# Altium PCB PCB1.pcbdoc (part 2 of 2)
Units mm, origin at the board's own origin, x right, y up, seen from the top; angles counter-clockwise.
Board outline 53.72 x 80.14 mm, 2 copper layers (Top Layer, Bottom Layer); 37 components, 55 nets, 218 pads, 259 vias.
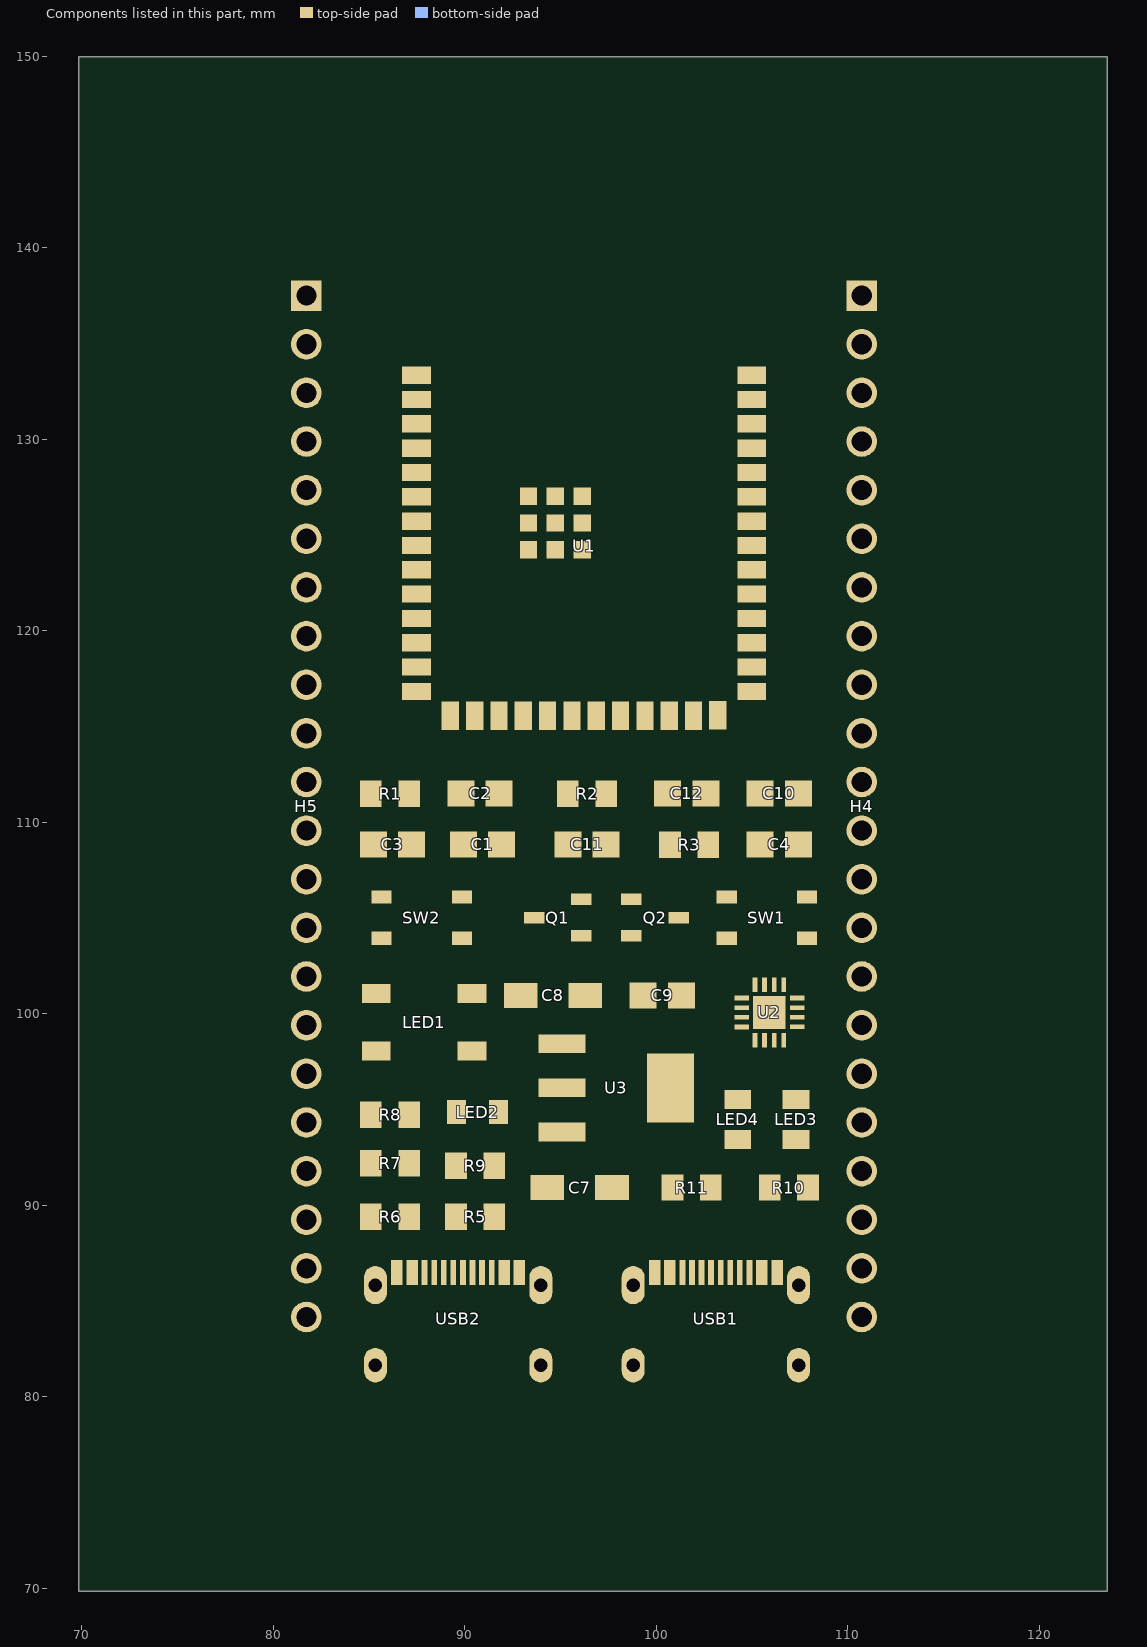
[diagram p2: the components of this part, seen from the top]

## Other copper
Top Layer:
  region net 5V_IN: 100.763,85.614 100.913,85.614 101.024,85.839 100.724,85.839
  region net $1N2384: 101.949,87.364 101.799,87.364 101.724,87.139 102.024,87.139
  region net CH_USB-: 102.449,87.364 102.299,87.364 102.224,87.139 102.524,87.139
  region net CH_USB-: 102.449,85.614 102.524,85.839 102.224,85.839 102.299,85.614
  region net CH_USB+: 102.949,87.364 102.799,87.364 102.724,87.139 103.024,87.139
  region net CH_USB-: 103.299,85.614 103.449,85.614 103.524,85.839 103.224,85.839
  region net CH_USB+: 103.961,87.364 103.811,87.364 103.724,87.139 104.024,87.139
  region net $1N2366: 104.977,87.364 104.827,87.364 104.724,87.139 105.024,87.139
  region net 5V_IN: 105.512,85.614 105.524,85.839 105.224,85.839 105.362,85.614
  region net 5V_IN: 105.589,87.364 105.524,87.139 105.824,87.139 105.739,87.364
  region net 3V3: 92.055,110.277 91.555,110.277 91.227,109.527 92.637,109.527
  region net 3V3: 92.025,112.73 91.525,112.73 91.1,112.194 92.51,112.194
  region net 3V3: 92.055,110.094 92.51,110.844 91.1,110.844 91.555,110.094
  region net CHIP_UP: 85.108,110.592 85.296,110.817 84.771,110.817 84.958,110.592
  region net CHIP_UP: 84.963,112.405 84.788,112.195 85.278,112.195 85.103,112.405
  region net CHIP_UP: 85.108,109.752 84.958,109.752 84.771,109.527 85.296,109.527
  region net CHIP_UP: 85.054,107.952 85.242,108.177 84.717,108.177 84.904,107.952
  region net CH_TX: 103.897,99.4 103.897,99.25 104.093,99.2 104.093,99.45
  region net CH_RX: 104.818,98.701 104.818,98.551 105.043,98.364 105.043,98.889
  region net $1N3062: 105.593,98.048 105.743,98.048 105.793,98.251 105.543,98.251
  region net CH_USB-: 106.952,98.109 106.952,98.321 106.793,99.001 106.545,98.251
  region net 5V_IN: 107.968,99.251 107.968,99.401 107.743,99.451 107.743,99.201
  region net DTR: 107.968,100.9 107.743,100.95 107.743,100.7 107.968,100.75
  region net RTS: 107.018,101.675 106.793,101.862 106.793,101.338 107.018,101.525
  region net RTS: 102.002,108.008 102.198,107.991 102.622,108.15 102.161,108.432
  region net $1N2059: 100.652,107.992 100.802,107.992 100.99,108.15 100.465,108.15
  region net CHIP_UP: 92.874,105.036 92.874,104.886 93.099,104.729 93.099,105.223
  region net CHIP_UP: 94.269,105.104 94.169,105.291 94.169,104.767 94.269,104.954
  region net $1N2059: 99.067,106.438 98.643,106.279 99.249,106.143 99.279,106.438
  region net DTR: 98.789,103.554 98.976,103.779 98.451,103.779 98.639,103.554
  region net DTR: 97.954,104.215 97.954,104.065 98.179,103.878 98.179,104.379
  region net GPIO0: 101.944,104.977 101.719,105.164 101.719,104.729 101.944,104.827
  region net 3V3: 107.576,107.727 107.951,108.177 106.901,108.177 107.276,107.727
  region net 5V_IN: 93.529,94.092 93.847,93.349 94.246,94.329 93.529,94.516
  region net 5V_IN: 94.476,92.899 94.776,92.899 95.151,93.349 94.101,93.349
  region net 5V_IN: 96.767,93.689 96.767,93.989 96.317,94.329 96.317,93.349
  region net 5V_IN: 94.367,89.862 94.742,90.284 93.692,90.284 94.067,89.862
  region net 5V_IN: 94.176,89.834 94.476,89.834 94.851,90.284 93.801,90.284
  region net 5V_IN: 94.476,92.03 94.101,91.58 95.151,91.58 94.776,92.03
  region net 3V3: 94.107,99.999 93.807,100.829 92.834,100.317 93.683,99.999
  region net GPIO48: 91.149,101.727 90.937,101.727 90.513,101.568 91.134,101.447
  region net 5V_IN: 87.301,85.614 87.451,85.614 87.562,85.839 87.262,85.839
  region net $1N3528: 88.487,87.229 88.337,87.229 88.262,87.139 88.562,87.139
  region net GPIO19: 88.987,87.364 88.837,87.364 88.762,87.139 89.062,87.139
  region net GPIO19: 88.987,85.614 89.062,85.839 88.762,85.839 88.837,85.614
  region net GPIO20: 89.337,87.364 89.262,87.139 89.562,87.139 89.487,87.364
  region net GPIO19: 89.987,85.614 90.062,85.839 89.762,85.839 89.837,85.614
  region net GPIO20: 90.337,87.364 90.262,87.139 90.562,87.139 90.487,87.364
  region net GPIO20: 90.487,85.614 90.562,85.839 90.262,85.839 90.337,85.614
  region net $1N3525: 91.487,87.364 91.337,87.364 91.262,87.139 91.562,87.139
  region net 5V_IN: 92.01,85.614 92.062,85.839 91.762,85.839 91.86,85.614
  region net $1N3528: 86.439,93.894 86.864,94.053 86.54,94.472 86.381,94.048
  region net GPIO0: 107.367,112.419 107.18,112.194 107.704,112.194 107.517,112.419
  region net GPIO0: 108.343,110.746 108.131,111.312 107.609,110.844 108.174,110.632
  region net GPIO0: 108.716,106.204 108.416,106.454 108.416,105.754 108.716,106.004
  region net GPIO0: 108.595,106.666 108.312,106.666 107.746,106.454 108.416,106.134
  region net CHIP_UP: 85.254,106.613 85.042,106.613 85.132,106.258 85.678,106.454
  region net CHIP_UP: 86.407,106.179 86.182,106.366 86.182,105.841 86.407,106.029
  region net CHIP_UP: 89.107,106.179 89.107,106.029 89.332,105.841 89.332,106.366
  region net CHIP_UP: 90.541,105.907 90.382,106.454 90.217,105.754 90.541,105.695
  region net CHIP_UP: 94.832,108.019 95.043,108.018 95.468,108.177 94.725,108.177
  region net 5V_IN: 103.53,111.708 103.305,111.895 103.305,111.371 103.53,111.558
  region net GPIO1: 109.942,135.023 109.725,134.064 109.831,133.958 110.79,134.175
  region net GPIO2: 109.942,132.483 109.725,131.524 109.831,131.418 110.79,131.635
  region net CH_TX: 110.79,128.151 109.871,128.328 109.765,128.222 109.942,127.303
  region net GPIO42: 111.056,125.548 110.049,125.991 109.905,125.923 109.971,125.035
  region net GPIO41: 111.252,122.888 110.692,123.317 110.542,123.317 110.066,122.704
  region net GPIO40: 110.79,120.531 109.831,120.748 109.725,120.642 109.942,119.683
  region net GPIO39: 110.79,117.991 109.831,118.208 109.725,118.102 109.942,117.143
  region net GPIO38: 110.239,115.277 109.41,115.327 109.4,115.124 110.184,114.078
  region net GPIO37: 111.34,112.642 110.815,113.034 110.665,113.034 110.14,112.642
  region net GPIO36: 110.79,110.371 109.831,110.588 109.725,110.482 109.942,109.523
  region net GPIO35: 110.79,107.831 109.831,108.048 109.725,107.942 109.942,106.983
  region net GPIO0: 111.251,105.108 110.249,105.793 110.004,105.755 110.066,104.923
  region net GPIO45: 110.79,102.751 109.831,102.968 109.725,102.862 109.942,101.903
  region net GPIO47: 111.538,96.823 111.755,97.782 111.649,97.888 110.69,97.671
  region net GPIO20: 110.102,91.31 110.059,90.48 110.256,90.465 111.299,91.221
  region net GPIO19: 110.211,89.853 109.7,89.328 109.7,89.178 110.211,88.653
  region net 3V3: 83.29,137.763 82.54,138.313 82.54,136.713 83.29,137.263
  region net 3V3: 82.29,134.392 83.109,134.751 83.091,135.251 82.248,135.591
  region net CHIP_UP: 82.269,131.833 83.1,132.358 83.1,132.508 82.269,133.033
  region net GPIO4: 82.269,129.293 83.1,129.818 83.1,129.968 82.269,130.493
  region net GPIO5: 82.269,126.753 82.854,127.278 82.854,127.428 82.269,127.953
  region net GPIO6: 82.539,124.853 82.696,125.79 82.578,125.884 81.601,125.601
  region net GPIO7: 82.429,122.68 82.458,123.52 82.28,123.554 81.25,122.906
  region net GPIO15: 82.517,119.925 82.595,120.821 82.455,120.894 81.453,120.48
  region net GPIO16: 82.538,117.143 82.755,118.102 82.649,118.208 81.69,117.991
  region net GPIO17: 82.538,114.603 82.755,115.562 82.649,115.668 81.69,115.451
  region net GPIO18: 82.538,112.063 82.755,113.022 82.649,113.128 81.69,112.911
  region net GPIO8: 82.538,109.523 82.755,110.482 82.649,110.588 81.69,110.371
  region net GPIO3: 82.538,106.983 82.755,107.942 82.649,108.048 81.69,107.831
  region net GPIO46: 82.538,104.443 82.755,105.402 82.649,105.508 81.69,105.291
  region net GPIO9: 82.538,101.903 82.755,102.862 82.649,102.968 81.69,102.751
  region net GPIO10: 82.538,99.363 82.755,100.322 82.649,100.428 81.69,100.211
  region net GPIO11: 82.538,96.823 82.755,97.782 82.649,97.888 81.69,97.671
  region net GPIO12: 82.538,94.283 82.772,95.224 82.631,95.365 81.69,95.131
  region net GPIO13: 82.538,91.743 82.755,92.702 82.649,92.808 81.69,92.591
  region net 5V_IN: 82.538,86.663 82.808,87.569 82.596,87.781 81.69,87.511
  region net $1N5776: 90.96,94.12 91.19,93.926 92.038,94.244 91.278,94.969
  region net $1N5776: 89.921,93.082 88.985,92.764 90.117,92.323 90.346,93.082
  region net CH_RX: 106.39,95.683 106.615,95.496 106.615,96.02 106.39,95.833
  region net $1N6033: 107.113,92.713 107.263,92.713 107.45,92.938 106.926,92.938
  region net CH_TX: 104.192,96.263 104.005,96.038 104.529,96.038 104.342,96.263
  region net 3V3: 106.084,89.932 106.459,90.243 105.409,90.243 105.784,89.932
  region net $1N6033: 107.361,91.78 107.368,91.508 107.998,91.621 107.573,91.78
  region net CHIP_UP: 86.515,130.89 86.515,130.74 86.74,130.552 86.74,131.077
  region net GPIO4: 86.515,129.968 86.515,129.818 86.74,129.631 86.74,129.995
  region net GPIO5: 86.515,128.35 86.515,128.2 86.74,128.012 86.74,128.537
  region net GPIO6: 86.515,127.075 86.515,126.925 86.74,126.738 86.74,127.262
  region net GPIO7: 86.515,125.406 86.74,125.285 86.74,125.743 86.515,125.556
  region net GPIO15: 86.515,124.54 86.515,124.39 86.74,124.202 86.74,124.727
  region net GPIO17: 86.515,122.104 86.74,121.916 86.74,122.375 86.515,122.254
  region net GPIO18: 86.515,120.73 86.515,120.58 86.74,120.392 86.74,120.917
  region net GPIO8: 86.515,119.564 86.74,119.376 86.74,119.835 86.515,119.714
  region net GPIO19: 86.515,118.19 86.515,118.04 86.74,117.852 86.74,118.377
  region net GPIO20: 86.515,116.92 86.515,116.77 86.74,116.582 86.74,117.107
  region net GPIO3: 88.769,114.656 88.981,114.656 89.405,114.815 88.805,114.957
  region net GPIO46: 90.45,114.655 90.6,114.655 90.787,114.815 90.263,114.815
  region net GPIO9: 91.72,114.59 91.87,114.59 92.057,114.815 91.533,114.815
  region net GPIO10: 93.267,114.59 93.454,114.815 92.93,114.815 93.117,114.59
  region net GPIO21: 99.614,114.656 99.826,114.656 99.865,114.882 98.965,114.815
  region net GPIO47: 100.76,114.59 100.947,114.815 100.423,114.815 100.61,114.59
  region net GPIO45: 103.834,115.092 103.675,115.516 103.604,114.845 103.834,114.88
  region net GPIO0: 105.965,116.765 105.965,116.915 105.74,117.102 105.74,116.578
  region net GPIO35: 105.965,118.04 105.965,118.19 105.74,118.377 105.74,117.852
  region net GPIO36: 105.965,119.31 105.965,119.46 105.74,119.647 105.74,119.122
  region net GPIO37: 105.965,120.58 105.965,120.73 105.74,120.917 105.74,120.392
  region net GPIO38: 105.965,121.85 105.965,122 105.74,122.187 105.74,121.662
  region net GPIO39: 105.965,123.12 105.965,123.27 105.74,123.457 105.74,122.932
  region net GPIO40: 105.965,124.39 105.965,124.54 105.74,124.727 105.74,124.202
  region net GPIO41: 105.965,125.937 105.74,126.124 105.74,125.599 105.965,125.787
  region net GPIO42: 105.965,126.93 105.965,127.08 105.74,127.267 105.74,126.742
  region net CH_TX: 105.965,128.2 105.965,128.35 105.74,128.537 105.74,128.012
  region net GPIO2: 105.965,130.74 105.965,130.89 105.74,131.077 105.74,130.552
  region net GPIO1: 105.965,132.01 105.965,132.16 105.74,132.347 105.74,131.822
  region net CH_TX: 105.192,128.046 105.509,128.2 105.509,128.35 105.192,128.504
  region net 5V_IN: 87.491,86.691 87.412,87.008 87.112,87.008 87.033,86.691
  region net 5V_IN: 87.125,86.217 87.301,85.946 87.451,86.006 87.55,86.387
  region net 5V_IN: 100.953,86.691 100.874,87.008 100.574,87.008 100.495,86.691
  region net 5V_IN: 100.587,86.217 100.763,85.946 100.913,86.006 101.012,86.387
  region net 5V_IN: 105.247,86.349 105.362,85.984 105.512,85.94 105.686,86.219
  region net 5V_IN: 105.82,86.551 105.739,86.95 105.589,87.027 105.413,86.761
  region net $1N3528: 86.877,94.761 86.761,94.428 86.867,94.322 87.2,94.438
  region net $1N3525: 90.52,90.502 90.683,90.221 90.833,90.36 90.856,90.812
  region net GPIO0: 107.587,106.123 107.523,105.842 107.629,105.736 107.91,105.8
  region net GPIO0: 108.093,105.875 108.41,106.004 108.41,106.204 108.093,106.333
  region net GPIO0: 108.195,106.085 108.328,106.4 108.187,106.541 107.872,106.408
  region net GPIO0: 103.762,105.807 104.08,105.736 104.155,105.873 103.976,106.212
  region net GPIO0: 103.387,106.123 103.271,105.79 103.377,105.684 103.71,105.8
  region net CHIP_UP: 84.805,114.352 84.963,114.035 85.103,114.035 85.262,114.352
  region net CHIP_UP: 87.288,131.044 86.971,130.89 86.971,130.74 87.288,130.586
  region net GPIO12: 86.385,99.493 86.514,99.176 86.714,99.176 86.843,99.493
  region net 3V3: 107.216,108.669 107.276,108.339 107.576,108.291 107.668,108.598
  region net 5V_IN: 102.818,111.404 103.135,111.558 103.135,111.708 102.818,111.862
  region net RTS: 99.262,104.8 99.579,104.954 99.579,105.104 99.262,105.258
  region net $1N3062: 105.46,97.517 105.576,97.85 105.47,97.956 105.137,97.84
  region net 5V_IN: 102.541,99.67 102.224,99.591 102.224,99.291 102.541,99.212
  region net 5V_IN: 102.762,99.745 102.542,99.748 102.436,99.642 102.439,99.422
  region net 5V_IN: 102.97,99.237 103.25,99.574 103.228,99.764 102.917,99.691
  region net DTR: 101.271,102.845 100.954,102.691 100.954,102.541 101.271,102.387
  region net GPIO48: 91.846,104.065 92,103.748 92.15,103.748 92.304,104.065
  region net GPIO48: 92.05,105.866 91.896,106.183 91.746,106.183 91.592,105.866
  region net GPIO19: 87.784,98.01 87.959,97.745 88.109,97.83 88.182,98.235
  region net GPIO20: 88.723,98.317 88.607,97.984 88.713,97.878 89.046,97.994
  region net GPIO19: 87.986,101.675 87.832,101.854 87.682,101.854 87.528,101.675
  region net GPIO20: 88.815,101.727 88.642,102.009 88.492,101.969 88.373,101.609
  region net GPIO20: 88.468,105.542 88.492,105.091 88.642,104.954 88.806,105.234
  region net GPIO19: 87.992,104.471 88.212,104.468 88.318,104.574 88.315,104.794
  region net GPIO19: 87.642,106.956 87.707,107.266 87.533,107.304 87.195,107.053
  region net GPIO20: 88.494,107.009 88.34,107.326 88.19,107.326 88.036,107.009
  region net $1N2384: 101.454,87.58 101.787,87.464 101.893,87.57 101.777,87.903
  region net 3V3: 106.157,90.105 106.084,90.426 105.784,90.442 105.7,90.129
  region net CH_USB-: 102.145,88.952 102.299,88.635 102.449,88.635 102.603,88.952
  region net CH_USB+: 103.657,88.952 103.811,88.635 103.961,88.635 104.115,88.952
  region net CH_USB+: 107.296,97.059 107.091,97.104 106.985,96.998 106.891,96.845
  region net CH_USB-: 107.29,97.865 107.136,98.106 106.986,98.106 106.832,97.865
  region net $1N2366: 104.673,88.063 104.827,87.746 104.977,87.746 105.131,88.063
  region net CH_TX: 103.149,98.604 103.303,98.287 103.453,98.287 103.607,98.604
  region net CH_TX: 103.682,98.787 103.798,99.12 103.692,99.226 103.359,99.11
  region net CH_RX: 104.038,98.35 104.192,98.033 104.342,98.033 104.496,98.35
  region net CH_RX: 104.518,98.379 104.802,98.551 104.764,98.701 104.407,98.823
  region net GPIO45: 106.677,107.721 106.501,107.988 106.351,107.92 106.261,107.53
  region net 3V3: 105.498,106.642 105.853,106.657 105.991,106.957 105.689,107.058
  region net 3V3: 104.927,104.954 105.006,104.637 105.306,104.637 105.385,104.954
  region net CH_RX: 106.02,103.453 105.866,103.77 105.716,103.77 105.562,103.453
  region net CH_RX: 108.916,105.302 108.913,105.082 109.019,104.976 109.239,104.979
  region net GPIO45: 106.451,104.192 106.605,103.886 106.755,103.886 106.909,104.192
  region net CH_TX: 102.845,105.866 102.691,106.183 102.541,106.183 102.387,105.866
  region net CH_TX: 103.53,114.044 103.684,113.727 103.834,113.727 103.988,114.044
  region net CH_TX: 103.988,112.851 103.834,113.168 103.684,113.168 103.53,112.851
  region net CH_TX: 103.359,109.805 103.692,109.689 103.798,109.795 103.682,110.128
  region net 5V_IN: 104.54,107.238 104.32,107.241 104.214,107.135 104.217,106.915
  region net 5V_IN: 103.756,104.992 103.706,104.701 103.871,104.654 104.208,104.921
  region net GPIO48: 99.543,108.025 99.389,108.342 99.239,108.342 99.085,108.025
  region net GPIO48: 108.223,102.285 108.003,102.288 107.897,102.182 107.9,101.962
  region net GPIO48: 99.01,114.065 99.007,113.845 99.113,113.739 99.333,113.742
  region net GPIO48: 99.112,114.275 98.795,114.121 98.795,113.971 99.112,113.817
  region net GPIO21: 101.922,110.344 101.653,110.543 101.547,110.437 101.47,110.273
  region net GPIO3: 83.591,110.288 83.745,109.971 83.895,109.971 84.049,110.288
  region net GPIO3: 88.569,114.027 88.685,114.36 88.579,114.466 88.246,114.35
  region net GPIO46: 83.591,107.748 83.745,107.431 83.895,107.431 84.049,107.748
  region net GPIO46: 89.585,113.392 89.701,113.725 89.595,113.831 89.262,113.715
  region net GPIO9: 84.099,105.97 84.253,105.653 84.403,105.653 84.557,105.97
  region net GPIO9: 89.864,110.007 90.181,110.161 90.181,110.311 89.864,110.465
  region net GPIO10: 83.897,102.762 83.894,102.542 84,102.436 84.22,102.439
  region net GPIO10: 84.505,102.724 84.508,102.944 84.402,103.05 84.182,103.047
  region net GPIO10: 85.904,103.226 85.587,103.072 85.587,102.922 85.904,102.768
  region net GPIO10: 89.737,102.768 90.054,102.922 90.054,103.072 89.737,103.226
  region net GPIO10: 90.83,104.065 90.984,103.748 91.134,103.748 91.288,104.065
  region net GPIO10: 91.288,106.7 91.134,106.934 90.984,106.934 90.83,106.7
  region net GPIO47: 109.041,117.373 109.22,117.527 109.22,117.677 109.041,117.831
  region net GPIO47: 102.033,113.767 101.727,113.613 101.727,113.463 102.033,113.309
  region net GPIO47: 100.456,115.363 100.61,115.047 100.76,115.047 100.914,115.363
  region net RTS: 107.24,101.829 106.923,101.675 106.923,101.525 107.24,101.371
  region net GPIO21: 108.604,97.84 108.271,97.956 108.165,97.85 108.281,97.517
  region net GPIO21: 107.489,98.279 107.809,98.206 107.882,98.345 107.703,98.684
  region net RTS: 108.356,95.683 108.51,95.366 108.66,95.366 108.814,95.683
  region net RTS: 98.45,98.096 98.604,97.779 98.754,97.779 98.908,98.096
  region net GPIO19: 89.244,85.347 88.965,85.385 88.906,85.232 89.173,84.895
  region net GPIO19: 89.643,84.895 89.91,85.232 89.859,85.393 89.572,85.347
  region net GPIO19: 90.988,82.814 91.317,82.959 91.329,83.109 91.024,83.27
  region net GPIO20: 90.663,85.315 90.487,85.581 90.337,85.504 90.255,85.106
  region net GPIO20: 91.896,83.464 92.213,83.618 92.213,83.768 91.896,83.922
  region net GPIO11: 83.808,99.292 83.743,98.982 83.917,98.944 84.255,99.196
  region net GPIO13: 83.337,94.286 83.491,93.969 83.641,93.969 83.795,94.286
  region net GPIO13: 96.445,113.386 96.128,113.232 96.128,113.082 96.445,112.928
  region net GPIO13: 94.463,107.39 94.309,107.707 94.159,107.707 94.005,107.39
  region net GPIO12: 87.097,101.675 86.943,101.992 86.793,101.992 86.639,101.675
  region net GPIO12: 86.639,103.557 86.793,103.24 86.943,103.24 87.097,103.557
  region net GPIO12: 93.524,106.401 93.207,106.247 93.207,106.097 93.524,105.943
  region net GPIO12: 92.437,106.249 92.77,106.133 92.876,106.239 92.76,106.572
  region net 3V3: 97.31,96.849 97.231,97.166 96.931,97.166 96.852,96.849
Bottom Layer:
  region net CH_RX: 110.107,130.383 109.459,129.353 109.493,129.175 110.333,129.204
  region net GPIO48: 110.79,100.211 109.831,100.428 109.725,100.322 109.942,99.363
  region net GPIO21: 111.34,94.862 110.815,95.381 110.665,95.381 110.14,94.862
  region net GPIO14: 82.538,89.203 82.755,90.162 82.649,90.268 81.69,90.051
  region net CH_TX: 104.788,128.504 104.472,128.35 104.472,128.2 104.788,128.046
  region net $1N3525: 86.952,92 87.106,91.683 87.256,91.683 87.41,92
  region net $1N3525: 90.349,91.034 90.032,90.88 90.032,90.73 90.349,90.576
  region net CHIP_UP: 85.296,114.71 85.165,115.057 85.015,115.085 84.846,114.795
  region net CHIP_UP: 87.288,131.044 86.971,130.89 86.971,130.74 87.288,130.586
  region net GPIO12: 86.918,99.676 86.921,99.896 86.815,100.002 86.595,99.999
  region net GPIO13: 96.664,115.345 96.826,115.04 96.976,115.053 97.12,115.384
  region net GPIO14: 97.934,115.345 98.096,115.04 98.246,115.053 98.39,115.384
  region net RTS: 98.858,105.258 98.541,105.104 98.541,104.954 98.858,104.8
  region net RTS: 95.875,105.777 96.029,105.46 96.179,105.46 96.333,105.777
  region net $1N2056: 95.092,111.304 95.245,110.987 95.395,110.987 95.549,111.304
  region net $1N2056: 96.022,104.373 95.704,104.443 95.635,104.3 95.823,103.961
  region net $1N3062: 101.101,100.763 101.255,100.446 101.405,100.446 101.559,100.763
  region net $1N3062: 104.877,97.66 104.61,97.484 104.678,97.334 105.068,97.244
  region net DTR: 101.675,102.387 101.992,102.541 101.992,102.691 101.675,102.845
  region net GPIO48: 92.094,104.571 91.874,104.574 91.768,104.468 91.771,104.248
  region net GPIO48: 91.592,105.462 91.746,105.145 91.896,105.145 92.05,105.462
  region net GPIO19: 88.127,98.482 87.982,98.811 87.832,98.822 87.671,98.516
  region net GPIO20: 89.127,98.586 88.952,98.64 88.802,98.64 88.729,98.361
  region net GPIO19: 87.657,101.185 87.832,100.92 87.982,101.005 88.055,101.41
  region net GPIO20: 88.627,101.169 88.824,101.189 88.93,101.295 88.95,101.492
  region net GPIO20: 89.002,105.739 88.848,106.056 88.698,106.056 88.544,105.739
  region net GPIO19: 88.223,104.994 88.062,105.299 87.912,105.287 87.767,104.958
  region net GPIO19: 87.268,106.522 87.607,106.343 87.746,106.416 87.673,106.736
  region net GPIO20: 88.246,106.503 88.579,106.387 88.685,106.493 88.569,106.826
  region net $1N2384: 86.877,89.206 87.031,88.889 87.181,88.889 87.335,89.206
  region net $1N2384: 101.271,88.113 100.954,87.959 100.954,87.809 101.271,87.655
  region net CH_USB-: 102.678,89.135 102.794,89.468 102.688,89.574 102.355,89.458
  region net CH_USB+: 104.115,89.356 103.961,89.673 103.811,89.673 103.657,89.356
  region net CH_USB+: 106.909,96.898 106.807,96.722 106.807,96.572 107.1,96.482
  region net CH_USB-: 106.757,97.682 106.641,97.349 106.747,97.243 107.08,97.359
  region net $1N2366: 91.532,89.104 91.865,88.988 91.971,89.094 91.855,89.427
  region net $1N2366: 104.921,88.569 104.701,88.572 104.595,88.466 104.598,88.246
  region net CH_TX: 103.682,98.787 103.798,99.12 103.692,99.226 103.359,99.11
  region net CH_RX: 104.571,98.533 104.687,98.866 104.581,98.972 104.248,98.856
  region net DTR: 103.684,102.845 103.367,102.691 103.367,102.541 103.684,102.387
  region net CH_RX: 105.192,129.316 105.509,129.47 105.509,129.62 105.192,129.774
  region net GPIO45: 106.429,107.163 106.605,106.896 106.755,106.964 106.845,107.354
  region net 3V3: 105.106,106.953 104.937,106.673 105.149,106.461 105.429,106.63
  region net 3V3: 105.28,105.435 105.179,105.737 104.879,105.599 104.864,105.244
  region net CH_RX: 105.487,103.27 105.371,102.937 105.477,102.831 105.81,102.947
  region net CH_RX: 109.524,105.264 109.527,105.484 109.421,105.59 109.201,105.587
  region net GPIO45: 106.909,104.596 106.755,104.913 106.605,104.913 106.451,104.596
  region net CH_TX: 102.387,105.462 102.541,105.145 102.691,105.145 102.845,105.462
  region net CH_TX: 104.063,114.227 104.066,114.447 103.96,114.553 103.74,114.55
  region net CH_TX: 103.53,112.447 103.684,112.13 103.834,112.13 103.988,112.447
  region net CH_TX: 103.682,110.09 103.798,110.423 103.692,110.529 103.359,110.413
  region net 5V_IN: 104.292,106.732 104.446,106.415 104.596,106.415 104.75,106.732
  region net 5V_IN: 104.317,105.137 104.433,105.47 104.327,105.576 103.994,105.46
  region net GPIO48: 99.295,107.519 99.628,107.403 99.734,107.509 99.618,107.842
  region net GPIO48: 103.684,102.083 103.367,101.929 103.367,101.779 103.684,101.625
  region net GPIO48: 108.185,101.677 108.518,101.561 108.624,101.667 108.508,102
  region net GPIO48: 101.726,115.363 101.88,115.047 102.03,115.047 102.184,115.363
  region net GPIO48: 99.516,113.817 99.833,113.971 99.833,114.121 99.516,114.275
  region net GPIO21: 101.498,109.907 101.652,109.59 101.802,109.59 101.956,109.907
  region net GPIO3: 84.049,110.692 83.895,111.009 83.745,111.009 83.591,110.692
  region net GPIO3: 87.961,114.065 87.845,113.732 87.951,113.626 88.284,113.742
  region net GPIO46: 84.049,108.152 83.895,108.469 83.745,108.469 83.591,108.152
  region net GPIO46: 88.977,113.43 88.861,113.097 88.967,112.991 89.3,113.107
  region net GPIO9: 84.557,106.374 84.403,106.691 84.253,106.691 84.099,106.374
  region net GPIO9: 89.46,110.465 89.143,110.311 89.143,110.161 89.46,110.007
  region net GPIO10: 86.308,102.768 86.625,102.922 86.625,103.072 86.308,103.226
  region net GPIO10: 89.333,103.226 89.016,103.072 89.016,102.922 89.333,102.768
  region net GPIO10: 91.288,104.469 91.134,104.786 90.984,104.786 90.83,104.469
  region net GPIO10: 90.83,106.296 90.984,105.98 91.134,105.98 91.288,106.296
  region net GPIO47: 108.548,117.695 108.382,117.356 108.461,117.223 108.783,117.302
  region net GPIO47: 102.437,113.309 102.754,113.463 102.754,113.613 102.437,113.767
  region net RTS: 107.423,101.296 107.756,101.18 107.862,101.286 107.746,101.619
  region net GPIO21: 108.566,97.232 108.899,97.116 109.005,97.222 108.889,97.555
  region net GPIO21: 107.437,98.88 107.104,98.996 106.998,98.89 107.114,98.557
  region net RTS: 108.814,96.087 108.66,96.266 108.51,96.266 108.356,96.087
  region net RTS: 98.908,98.5 98.754,98.817 98.604,98.817 98.45,98.5
  region net GPIO19: 89.284,84.811 89.46,84.544 89.61,84.612 89.7,85.002
  region net GPIO19: 90.824,83.362 90.491,83.478 90.385,83.372 90.501,83.039
  region net GPIO20: 90.322,84.829 90.476,84.512 90.626,84.512 90.78,84.829
  region net GPIO20: 91.492,83.922 91.175,83.768 91.175,83.618 91.492,83.464
  region net GPIO11: 84.378,99.422 84.494,99.755 84.388,99.861 84.055,99.745
  region net GPIO11: 94.124,115.345 94.286,115.04 94.436,115.053 94.58,115.384
  region net GPIO13: 83.823,94.652 83.892,94.962 83.708,94.99 83.371,94.723
  region net GPIO12: 95.376,115.363 95.53,115.047 95.68,115.047 95.834,115.363
  region net GPIO13: 96.951,113.138 96.954,113.358 96.848,113.464 96.628,113.461
  region net GPIO13: 94.215,106.884 94.435,106.881 94.541,106.987 94.538,107.207
  region net GPIO12: 86.639,101.271 86.793,100.954 86.943,100.954 87.097,101.271
  region net GPIO12: 87.172,103.74 87.288,104.073 87.182,104.179 86.849,104.063
  region net GPIO12: 94.018,106.26 93.928,106.553 93.778,106.553 93.602,106.451
  region net GPIO12: 92.475,106.857 92.142,106.973 92.036,106.867 92.152,106.534

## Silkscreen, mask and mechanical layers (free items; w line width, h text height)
Top Silkscreen Layer:
  text "POWER" at 88.907,95.967 h1.13
Bottom Silkscreen Layer:
  text "3V3" at 84.781,137.255 h0.65
  text "GND /  " at 109.165,136.366 h0.65
  text "3V3" at 84.781,134.715 h0.65
  text "IO1" at 109.165,134.588 h0.65
  text "RST" at 84.654,132.175 h0.65
  text "IO2" at 109.292,132.136 h0.65
  text "IO4" at 84.4,129.635 h0.65
  text "RX" at 109.193,129.508 h0.65
  text "IO5" at 84.4,127.095 h0.65
  text "TX" at 109.193,127.095 h0.65
  text "IO6" at 84.4,124.555 h0.65
  text "IO42" at 109.39,124.516 h0.65
  text "IO7" at 84.4,122.015 h0.65
  text "IO41" at 109.39,121.722 h0.65
  text "IO15" at 84.625,119.475 h0.65
  text "IO40" at 109.39,119.309 h0.65
  text "IO16" at 84.625,116.935 h0.65
  text "IO39" at 109.263,116.642 h0.65
  text "IO17" at 84.625,114.395 h0.65
  text "IO38" at 109.263,114.356 h0.65
  text "IO18" at 84.752,111.855 h0.65
  text "IO37" at 109.322,111.779 h0.65
  text "IO36" at 109.322,109.299 h0.65
  text "IO8" at 84.4,109.188 h0.65
  text "IO35" at 109.39,106.863 h0.65
  text "IO3" at 84.4,106.775 h0.65
  text "IO46" at 84.879,104.235 h0.65
  text "IO0" at 109.419,104.108 h0.65
  text "IO45" at 109.39,102.203 h0.65
  text "IO9" at 84.527,101.695 h0.65
  text "IO10" at 84.752,99.536 h0.65
  text "IO48" at 109.368,99.215 h0.65
  text "IO11" at 84.625,96.615 h0.65
  text "IO47" at 109.39,96.449 h0.65
  text "IO12" at 85.641,94.075 h0.65
  text "IO21" at 109.39,94.036 h0.65
  text "IO13" at 84.752,91.623 h0.65
  text "IO20" at 109.39,91.496 h0.65
  text "IO14" at 84.752,89.083 h0.65
  text "IO19" at 109.39,88.956 h0.65
  text "GND" at 109.419,86.924 h0.65
  text "5V" at 84.555,86.455 h0.65
  text "GND" at 109.419,83.915 h0.65
  text "GND" at 84.781,83.876 h0.65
